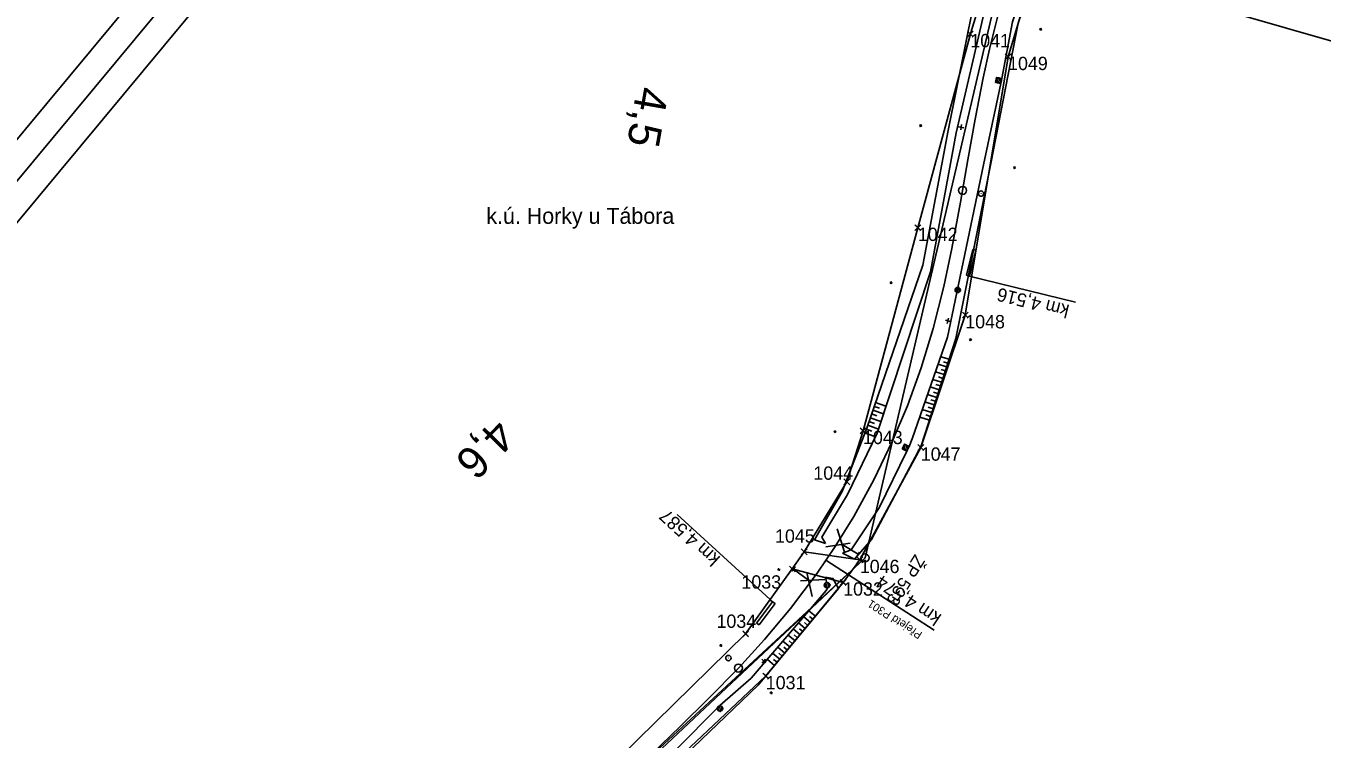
# Model space of a CAD drawing. Extents: x -738085 to -734426, y -1122197 to -1119748.
# Drawn here: x -737687.7 to -737444.6, y -1121665.2 to -1121531.4 of the extents above; entities that cross this region are included whole.
import ezdxf

# ---------------------------------------------------------------- set-up
doc = ezdxf.new("R2010")
doc.units = 0
for name, color, linetype in [('Polygon ku', 7, 'Continuous'), ('SŽDC', 7, 'Continuous'), ('Trvalý zábor', 7, 'Continuous'), ('Vrstva 1', 7, 'Continuous'), ('Vrstva 11', 7, 'Continuous'), ('Vrstva 12', 7, 'Continuous'), ('Vrstva 4', 7, 'Continuous'), ('Vrstva 48', 7, 'Continuous'), ('Vrstva 49', 7, 'Continuous'), ('Vrstva 60', 7, 'Continuous'), ('Vrstva 63', 7, 'Continuous'), ('Vrstva 7', 7, 'Continuous'), ('Vrstva 9', 7, 'Continuous')]:
    doc.layers.add(name, color=color, linetype=linetype)

msp = doc.modelspace()

# ---------------------------------------------------------------- linework, layer by layer
at = {"layer": 'SŽDC'}
for p, q in [((-737520.44, -1121569.24), (-737510.61, -1121532.89)), ((-737531.34, -1121631.55), (-737541.78, -1121630.08)), ((-737544, -1121633.28), (-737534.46, -1121635.79)), ((-737534.46, -1121635.79), (-737548.98, -1121653.36))]:
    msp.add_line(p, q, dxfattribs=at)
for points in [[(-737510.61, -1121532.89), (-737503.77, -1121510.31), (-737493.54, -1121488.02), (-737480.94, -1121469.09), (-737466.82, -1121455.14)], [(-737465.87, -1121468.59), (-737481.22, -1121487.43), (-737485.71, -1121494.9), (-737493.58, -1121508.22), (-737499.12, -1121522.51), (-737503.53, -1121537.17)], [(-737503.53, -1121537.17), (-737511.56, -1121585.63), (-737519.9, -1121610.47), (-737531.34, -1121631.55)], [(-737541.78, -1121630.08), (-737533.76, -1121616.93), (-737530.74, -1121607.35), (-737520.44, -1121569.24)], [(-737596.72, -1121688.63), (-737552.76, -1121645.44), (-737544, -1121633.28)], [(-737548.98, -1121653.36), (-737584.84, -1121687.15), (-737585.89, -1121688.17)]]:
    msp.add_lwpolyline(points, dxfattribs=at)
at = {"layer": 'Trvalý zábor'}
for p, q in [((-737544, -1121633.28), (-737541.78, -1121630.08)), ((-737541.78, -1121630.08), (-737544, -1121633.28)), ((-737531.34, -1121631.55), (-737541.78, -1121630.08)), ((-737544, -1121633.28), (-737534.46, -1121635.79)), ((-737534.46, -1121635.79), (-737531.34, -1121631.55))]:
    msp.add_line(p, q, dxfattribs=at)
at = {"layer": 'Vrstva 1'}
for points in [[(-736726.43, -1121430.48), (-737533.93, -1121199.12), (-737615.73, -1121484.62), (-736808.23, -1121715.98)], [(-737452.56, -1121267.51), (-737989.34, -1121913.61), (-737760.91, -1122103.4), (-737224.12, -1121457.29)], [(-737982.3, -1121912.96), (-737451.91, -1121274.55), (-737231.17, -1121457.94), (-737761.56, -1122096.35)], [(-737451.26, -1121281.58), (-737844.27, -1121754.63), (-737631.21, -1121931.64), (-737238.2, -1121458.59)]]:
    msp.add_lwpolyline(points, close=True, dxfattribs=at)
msp.add_lwpolyline([(-737505.35, -1121528.98), (-737507.02, -1121535.76), (-737508.18, -1121541.1), (-737509.7, -1121548.87), (-737511.05, -1121556.54), (-737512.45, -1121564.46), (-737514.07, -1121573.14), (-737515.6, -1121580.26), (-737517.59, -1121588.18), (-737519.85, -1121595.56), (-737522.41, -1121602.65), (-737525.26, -1121609.39), (-737528.71, -1121616.54), (-737532.49, -1121623.46), (-737535.97, -1121629.07), (-737539.35, -1121634.1), (-737544.33, -1121640.72), (-737549.2, -1121646.51), (-737554.12, -1121651.88), (-737559.65, -1121657.52), (-737565.05, -1121662.86), (-737573.92, -1121671.42), (-737588.06, -1121684.98)], dxfattribs=at)
msp.add_lwpolyline([(-737505.35, -1121528.98), (-737507.02, -1121535.76), (-737508.18, -1121541.1), (-737509.7, -1121548.87), (-737511.05, -1121556.54), (-737512.45, -1121564.46), (-737514.07, -1121573.14), (-737515.6, -1121580.26), (-737517.59, -1121588.18), (-737519.85, -1121595.56), (-737522.41, -1121602.65), (-737525.26, -1121609.39), (-737528.71, -1121616.54), (-737532.49, -1121623.46), (-737535.97, -1121629.07), (-737539.35, -1121634.1), (-737544.33, -1121640.72), (-737549.2, -1121646.51), (-737554.12, -1121651.88), (-737559.65, -1121657.52), (-737565.05, -1121662.86), (-737573.92, -1121671.42), (-737588.06, -1121684.98)], dxfattribs=at)
at = {"layer": 'Vrstva 11'}
for p, q in [((-737505.38, -1121541.13), (-737504.88, -1121541.9)), ((-737505.69, -1121541.33), (-737505.19, -1121542.1)), ((-737513.36, -1121580.62), (-737512.88, -1121581.41)), ((-737513.04, -1121580.43), (-737512.57, -1121581.22)), ((-737523.08, -1121610.15), (-737522.74, -1121611.01)), ((-737522.73, -1121610.01), (-737522.39, -1121610.86)), ((-737537.73, -1121635.89), (-737537.6, -1121636.8)), ((-737537.36, -1121635.84), (-737537.23, -1121636.75)), ((-737557.74, -1121659.01), (-737557.75, -1121659.93)), ((-737557.37, -1121659.02), (-737557.38, -1121659.93))]:
    msp.add_line(p, q, dxfattribs=at)
for centre in [(-737505.29, -1121541.62), (-737512.97, -1121580.92), (-737522.74, -1121610.51), (-737537.49, -1121636.32), (-737557.57, -1121659.47)]:
    msp.add_circle(centre, 0.5, dxfattribs=at)
at = {"layer": 'Vrstva 12'}
for p, q in [((-737504.71, -1121541.22), (-737504.9, -1121542.2)), ((-737522.08, -1121610.28), (-737522.51, -1121611.18)), ((-737536.9, -1121636.24), (-737537.4, -1121636.9))]:
    msp.add_line(p, q, dxfattribs=at)
for points in [[(-737505.88, -1121542.01), (-737505.69, -1121541.03), (-737504.71, -1121541.22), (-737504.9, -1121542.2), (-737505.88, -1121542.01)], [(-737505.69, -1121541.03), (-737504.71, -1121541.22), (-737504.71, -1121541.22)], [(-737505.88, -1121542.01), (-737504.9, -1121542.2), (-737504.9, -1121542.2)], [(-737523.41, -1121610.74), (-737522.98, -1121609.84), (-737522.08, -1121610.28), (-737522.51, -1121611.18), (-737523.41, -1121610.74)], [(-737523.41, -1121610.74), (-737522.51, -1121611.18), (-737522.51, -1121611.18)], [(-737522.98, -1121609.84), (-737522.08, -1121610.28), (-737522.08, -1121610.28)], [(-737538.07, -1121636.4), (-737537.57, -1121635.74), (-737536.9, -1121636.24), (-737537.4, -1121636.9), (-737538.07, -1121636.4)], [(-737537.57, -1121635.74), (-737536.9, -1121636.24), (-737536.9, -1121636.24)], [(-737538.07, -1121636.4), (-737537.4, -1121636.9), (-737537.4, -1121636.9)], [(-737558.15, -1121659.48), (-737557.57, -1121658.88), (-737556.98, -1121659.46), (-737557.56, -1121660.06), (-737558.15, -1121659.48)]]:
    msp.add_lwpolyline(points, dxfattribs=at)
at = {"layer": 'Vrstva 4'}
for p, q in [((-737534.19, -1121630.14), (-737535.58, -1121625.74)), ((-737537.69, -1121629.14), (-737533.14, -1121628.44)), ((-737531.67, -1121630.53), (-737534.64, -1121628.68)), ((-737535.97, -1121629.07), (-737539.35, -1121634.1)), ((-737531.93, -1121630.95), (-737531.4, -1121630.1)), ((-737543.46, -1121632.91), (-737544.07, -1121633.71)), ((-737543.77, -1121633.31), (-737540.97, -1121635.41)), ((-737537.7, -1121631.65), (-737517.39, -1121644.79)), ((-737537.89, -1121635.23), (-737542.49, -1121635.52)), ((-737541.29, -1121633.92), (-737540.29, -1121638.42))]:
    msp.add_line(p, q, dxfattribs=at)
at = {"layer": 'Vrstva 48'}
for p, q in [((-737514.61, -1121593.94), (-737516.16, -1121593.45)), ((-737514.84, -1121594.66), (-737515.62, -1121594.41)), ((-737515.53, -1121596.8), (-737517.15, -1121596.28)), ((-737515.07, -1121595.37), (-737516.65, -1121594.86)), ((-737515.3, -1121596.08), (-737516.1, -1121595.83)), ((-737516.45, -1121599.65), (-737518.14, -1121599.11)), ((-737515.99, -1121598.23), (-737517.64, -1121597.7)), ((-737516.22, -1121598.94), (-737517.06, -1121598.67)), ((-737515.76, -1121597.51), (-737516.58, -1121597.25)), ((-737517.37, -1121602.51), (-737519.12, -1121601.95)), ((-737516.91, -1121601.08), (-737518.63, -1121600.53)), ((-737517.14, -1121601.8), (-737518.01, -1121601.52)), ((-737516.68, -1121600.37), (-737517.53, -1121600.09)), ((-737529.13, -1121604.19), (-737528.13, -1121604.54)), ((-737528.89, -1121603.48), (-737526.9, -1121604.17)), ((-737528.64, -1121602.77), (-737527.65, -1121603.11)), ((-737528.4, -1121602.06), (-737526.43, -1121602.74)), ((-737517.83, -1121603.94), (-737519.62, -1121603.36)), ((-737518.06, -1121604.65), (-737518.96, -1121604.36)), ((-737517.6, -1121603.22), (-737518.49, -1121602.94)), ((-737529.86, -1121606.32), (-737527.83, -1121607.02)), ((-737529.62, -1121605.61), (-737528.61, -1121605.96)), ((-737529.37, -1121604.9), (-737527.37, -1121605.59)), ((-737518.29, -1121605.36), (-737520.11, -1121604.78)), ((-737530.38, -1121607.73), (-737528.42, -1121608.48)), ((-737530.11, -1121607.03), (-737529.1, -1121607.42)), ((-737540.6, -1121643.3), (-737541.86, -1121642.26)), ((-737539.65, -1121642.15), (-737540.88, -1121641.12)), ((-737540.12, -1121642.72), (-737540.75, -1121642.21)), ((-737543.48, -1121646.76), (-737544.78, -1121645.68)), ((-737542.52, -1121645.61), (-737543.81, -1121644.54)), ((-737543, -1121646.18), (-737543.65, -1121645.65)), ((-737541.56, -1121644.45), (-737542.83, -1121643.4)), ((-737542.04, -1121645.03), (-737542.68, -1121644.5)), ((-737541.08, -1121643.88), (-737541.71, -1121643.35)), ((-737545.4, -1121649.07), (-737546.73, -1121647.96)), ((-737544.44, -1121647.92), (-737545.76, -1121646.82)), ((-737544.92, -1121648.49), (-737545.58, -1121647.94)), ((-737543.96, -1121647.34), (-737544.61, -1121646.79)), ((-737547.32, -1121651.38), (-737548.68, -1121650.24)), ((-737546.36, -1121650.22), (-737547.7, -1121649.1)), ((-737546.84, -1121650.8), (-737547.51, -1121650.24)), ((-737545.88, -1121649.65), (-737546.55, -1121649.09))]:
    msp.add_line(p, q, dxfattribs=at)
at = {"layer": 'Vrstva 49'}
for p, q in [((-737497.21, -1121531.88), (-737497.64, -1121532.14)), ((-737497.55, -1121531.8), (-737497.29, -1121532.22)), ((-737519.73, -1121549.95), (-737520.14, -1121550.23)), ((-737520.08, -1121549.88), (-737519.79, -1121550.29)), ((-737502.13, -1121557.84), (-737502.54, -1121558.13)), ((-737502.48, -1121557.78), (-737502.19, -1121558.19)), ((-737525.26, -1121579.46), (-737525.69, -1121579.71)), ((-737525.61, -1121579.37), (-737525.35, -1121579.8)), ((-737510.36, -1121590.15), (-737510.8, -1121590.38)), ((-737510.7, -1121590.04), (-737510.46, -1121590.48)), ((-737535.75, -1121607.44), (-737536.22, -1121607.61)), ((-737536.07, -1121607.29), (-737535.9, -1121607.76)), ((-737516.13, -1121611.5), (-737516.59, -1121611.69)), ((-737516.45, -1121611.36), (-737516.26, -1121611.82)), ((-737546.28, -1121633.35), (-737546.77, -1121633.42)), ((-737546.56, -1121633.14), (-737546.49, -1121633.63)), ((-737557.14, -1121647.64), (-737557.64, -1121647.66)), ((-737557.4, -1121647.4), (-737557.37, -1121647.9)), ((-737547.69, -1121656.5), (-737548.19, -1121656.52)), ((-737547.95, -1121656.26), (-737547.93, -1121656.76))]:
    msp.add_line(p, q, dxfattribs=at)
for points in [[(-737355.47, -1121412.32), (-737367.21, -1121412.69), (-737377.95, -1121412.78), (-737396.2, -1121415.99), (-737409.71, -1121420.96), (-737428.4, -1121428.4), (-737447.9, -1121440), (-737466.76, -1121457.31), (-737479.09, -1121469.07), (-737494.02, -1121491.43), (-737502.64, -1121510.6), (-737503.11, -1121511.74), (-737503.41, -1121512.48), (-737507.86, -1121528.05), (-737513.25, -1121551.43), (-737518.11, -1121577.51), (-737528.1, -1121607.82), (-737533.62, -1121619.3), (-737538.45, -1121627.34), (-737537.78, -1121628.5)], [(-737433.88, -1121443.3), (-737441.92, -1121447.46), (-737446.73, -1121454.15), (-737450.86, -1121456.72), (-737454.77, -1121457.18), (-737455.53, -1121457.22), (-737473.31, -1121474.96), (-737487.17, -1121494.48), (-737497.62, -1121515.22), (-737502.7, -1121530.64), (-737504.71, -1121541.22), (-737504.9, -1121542.2), (-737508.13, -1121557.44), (-737514.88, -1121589.78), (-737521.54, -1121608.87), (-737522.08, -1121610.28), (-737522.51, -1121611.18), (-737527.69, -1121621.79), (-737532.98, -1121629.72), (-737534.58, -1121630.34)], [(-737537.78, -1121628.5), (-737539.82, -1121627.79), (-737534.62, -1121618.75), (-737530.05, -1121606.87), (-737519.54, -1121576.25), (-737514.78, -1121551.01), (-737510.02, -1121527.4), (-737503.65, -1121510.06), (-737494.02, -1121491.43)], [(-737534.58, -1121630.34), (-737532.35, -1121631.42), (-737529.16, -1121627.74), (-737519.85, -1121610.2), (-737513.36, -1121590.05), (-737506.75, -1121557.21), (-737501.66, -1121530.87), (-737496.47, -1121515.67), (-737487.17, -1121494.48)], [(-737537.78, -1121634.82), (-737536.39, -1121635.05), (-737535.35, -1121636.97), (-737550.38, -1121655.07), (-737571.7, -1121675.53), (-737591.99, -1121695.03), (-737627.26, -1121728.64), (-737670.99, -1121771.4), (-737684.23, -1121784.32), (-737686.26, -1121783.92), (-737687.29, -1121782.58)], [(-737537.78, -1121634.82), (-737537.57, -1121635.74), (-737536.9, -1121636.24), (-737537.4, -1121636.9), (-737537.63, -1121637.32), (-737551.7, -1121653.77), (-737557.57, -1121658.88), (-737558.15, -1121659.48), (-737572.93, -1121674.36), (-737592.85, -1121693.86), (-737604.17, -1121704.88), (-737604.75, -1121705.43), (-737627.7, -1121727.82), (-737671.73, -1121770.2), (-737684.57, -1121782.83), (-737686.26, -1121783.92)]]:
    msp.add_lwpolyline(points, dxfattribs=at)
at = {"layer": 'Vrstva 60'}
for p, q in [((-737510.16, -1121533.34), (-737511.16, -1121532.34)), ((-737510.16, -1121532.44), (-737511.16, -1121533.44)), ((-737511.06, -1121533.34), (-737510.06, -1121532.34)), ((-737511.06, -1121532.44), (-737510.06, -1121533.44)), ((-737510.61, -1121532.89), (-737510.61, -1121532.89)), ((-737503.08, -1121537.62), (-737504.08, -1121536.62)), ((-737503.08, -1121536.72), (-737504.08, -1121537.72)), ((-737503.98, -1121537.62), (-737502.98, -1121536.62)), ((-737503.98, -1121536.72), (-737502.98, -1121537.72)), ((-737503.53, -1121537.17), (-737503.53, -1121537.17)), ((-737519.99, -1121569.69), (-737520.99, -1121568.69)), ((-737519.99, -1121568.79), (-737520.99, -1121569.79)), ((-737520.89, -1121569.69), (-737519.89, -1121568.69)), ((-737520.89, -1121568.79), (-737519.89, -1121569.79)), ((-737520.44, -1121569.24), (-737520.44, -1121569.24)), ((-737511.11, -1121586.08), (-737512.11, -1121585.08)), ((-737511.11, -1121585.18), (-737512.11, -1121586.18)), ((-737512.01, -1121586.08), (-737511.01, -1121585.08)), ((-737512.01, -1121585.18), (-737511.01, -1121586.18)), ((-737511.56, -1121585.63), (-737511.56, -1121585.63)), ((-737530.29, -1121607.8), (-737531.29, -1121606.8)), ((-737531.19, -1121607.8), (-737530.19, -1121606.8)), ((-737530.29, -1121606.9), (-737531.29, -1121607.9)), ((-737531.19, -1121606.9), (-737530.19, -1121607.9)), ((-737530.74, -1121607.35), (-737530.74, -1121607.35)), ((-737519.45, -1121610.92), (-737520.45, -1121609.92)), ((-737519.45, -1121610.02), (-737520.45, -1121611.02)), ((-737520.35, -1121610.92), (-737519.35, -1121609.92)), ((-737520.35, -1121610.02), (-737519.35, -1121611.02)), ((-737519.9, -1121610.47), (-737519.9, -1121610.47)), ((-737533.31, -1121617.38), (-737534.31, -1121616.38)), ((-737533.31, -1121616.48), (-737534.31, -1121617.48)), ((-737534.21, -1121617.38), (-737533.21, -1121616.38)), ((-737534.21, -1121616.48), (-737533.21, -1121617.48)), ((-737533.76, -1121616.93), (-737533.76, -1121616.93)), ((-737541.33, -1121630.53), (-737542.33, -1121629.53)), ((-737541.33, -1121629.63), (-737542.33, -1121630.63)), ((-737542.23, -1121630.53), (-737541.23, -1121629.53)), ((-737542.23, -1121629.63), (-737541.23, -1121630.63)), ((-737541.78, -1121630.08), (-737541.78, -1121630.08)), ((-737530.89, -1121632), (-737531.89, -1121631)), ((-737530.89, -1121631.1), (-737531.89, -1121632.1)), ((-737531.79, -1121632), (-737530.79, -1121631)), ((-737531.79, -1121631.1), (-737530.79, -1121632.1)), ((-737543.55, -1121633.73), (-737544.55, -1121632.73)), ((-737543.55, -1121632.83), (-737544.55, -1121633.83)), ((-737544.45, -1121633.73), (-737543.45, -1121632.73)), ((-737544.45, -1121632.83), (-737543.45, -1121633.83)), ((-737544, -1121633.28), (-737544, -1121633.28)), ((-737531.34, -1121631.55), (-737531.34, -1121631.55)), ((-737534.01, -1121636.24), (-737535.01, -1121635.24)), ((-737534.01, -1121635.34), (-737535.01, -1121636.34)), ((-737534.91, -1121636.24), (-737533.91, -1121635.24)), ((-737534.91, -1121635.34), (-737533.91, -1121636.34)), ((-737534.46, -1121635.79), (-737534.46, -1121635.79)), ((-737552.31, -1121645.89), (-737553.31, -1121644.89)), ((-737552.31, -1121644.99), (-737553.31, -1121645.99)), ((-737553.21, -1121645.89), (-737552.21, -1121644.89)), ((-737553.21, -1121644.99), (-737552.21, -1121645.99)), ((-737552.76, -1121645.44), (-737552.76, -1121645.44)), ((-737548.53, -1121653.81), (-737549.53, -1121652.81)), ((-737548.53, -1121652.91), (-737549.53, -1121653.91)), ((-737549.43, -1121653.81), (-737548.43, -1121652.81)), ((-737549.43, -1121652.91), (-737548.43, -1121653.91)), ((-737548.98, -1121653.36), (-737548.98, -1121653.36))]:
    msp.add_line(p, q, dxfattribs=at)
at = {"layer": 'Vrstva 63'}
for p, q in [((-737530.36, -1121631.2), (-737502.71, -1121512.73)), ((-737530.33, -1121631.16), (-737530.38, -1121631.24)), ((-737696.42, -1121784.79), (-737530.36, -1121631.2)), ((-737691.07, -1121781.8), (-737530.36, -1121631.2))]:
    msp.add_line(p, q, dxfattribs=at)
msp.add_circle((-737530.36, -1121631.2), 0.756, dxfattribs=at)
at = {"layer": 'Vrstva 7'}
for p, q in [((-737511.84, -1121550.49), (-737512.82, -1121550.32)), ((-737512.24, -1121549.91), (-737512.42, -1121550.9)), ((-737508.59, -1121562.8), (-737508.6, -1121562.9)), ((-737514.33, -1121586.83), (-737515.3, -1121586.59)), ((-737514.69, -1121586.22), (-737514.94, -1121587.19)), ((-737555.96, -1121649.96), (-737556.03, -1121650.03)), ((-737548.97, -1121650.91), (-737549.7, -1121650.23)), ((-737549, -1121650.2), (-737549.67, -1121650.94))]:
    msp.add_line(p, q, dxfattribs=at)
for centre, radius in [((-737512.06, -1121562.24), 0.75), ((-737512.06, -1121562.24), 0.75), ((-737508.59, -1121562.85), 0.5), ((-737555.99, -1121649.99), 0.5), ((-737554.12, -1121651.88), 0.75), ((-737554.12, -1121651.88), 0.75)]:
    msp.add_circle(centre, radius, dxfattribs=at)
at = {"layer": 'Vrstva 9'}
for p, q in [((-737510.14, -1121573.32), (-737511.35, -1121578.17)), ((-737510.77, -1121578.32), (-737509.55, -1121573.47)), ((-737509.55, -1121573.47), (-737510.14, -1121573.32)), ((-737511.35, -1121578.17), (-737510.77, -1121578.32)), ((-737511.06, -1121578.25), (-737490.9, -1121583.24)), ((-737510.77, -1121578.32), (-737510.19, -1121578.47)), ((-737547.48, -1121639.61), (-737565.58, -1121623.06)), ((-737547.72, -1121639.43), (-737550.72, -1121643.42)), ((-737550.24, -1121643.78), (-737547.24, -1121639.79)), ((-737547.72, -1121639.43), (-737548.2, -1121639.07)), ((-737547.24, -1121639.79), (-737547.72, -1121639.43)), ((-737550.72, -1121643.42), (-737550.24, -1121643.78))]:
    msp.add_line(p, q, dxfattribs=at)

# ---------------------------------------------------------------- texts
at = {"layer": 'Polygon ku'}
msp.add_text('k.ú. Horky u Tábora', height=3, dxfattribs=at).set_placement((-737601.38, -1121568.52))
at = {"layer": 'Vrstva 4'}
for s, height, rotation, p in [('km 4,574', 2.5, 146.0712, (-737515.83, -1121641.98)), ('Přejetd P301', 1.5, 147.1107, (-737519.5, -1121645.27))]:
    msp.add_text(s, height=height, rotation=rotation, dxfattribs=at).set_placement(p)
at = {"layer": 'Vrstva 60'}
for s, p in [('1041', (-737510.61, -1121535.39)), ('1049', (-737503.53, -1121539.67)), ('1042', (-737520.44, -1121571.74)), ('1048', (-737511.56, -1121588.13)), ('1043', (-737530.74, -1121609.85)), ('1047', (-737519.9, -1121612.97)), ('1044', (-737540.05, -1121616.54)), ('1045', (-737547.24, -1121628.35)), ('1046', (-737531.34, -1121634.05)), ('1033', (-737553.54, -1121636.97)), ('1032', (-737534.46, -1121638.29)), ('1034', (-737558.22, -1121644.33)), ('1031', (-737548.98, -1121655.86))]:
    msp.add_text(s, height=2.5, dxfattribs=at).set_placement(p)
at = {"layer": 'Vrstva 63'}
msp.add_text('ŽP 533', height=2.4, rotation=238.1713, dxfattribs=at).set_placement((-737520.99, -1121630.38))
at = {"layer": 'Vrstva 7'}
for s, rotation, p in [('4,5', 259.9941, (-737573.08, -1121542.55)), ('4,5', 259.9941, (-737573.08, -1121542.55)), ('4,6', 225.5695, (-737599.74, -1121604.74)), ('4,6', 225.5695, (-737599.74, -1121604.74))]:
    msp.add_text(s, height=6, rotation=rotation, dxfattribs=at).set_placement(p)
at = {"layer": 'Vrstva 9'}
for s, rotation, p in [('km 4,516', 166.0915, (-737491.88, -1121583.78)), ('km 4,587', 137.5635, (-737557.34, -1121631.14))]:
    msp.add_text(s, height=2.5, rotation=rotation, dxfattribs=at).set_placement(p)

doc.saveas('drawing.dxf')
